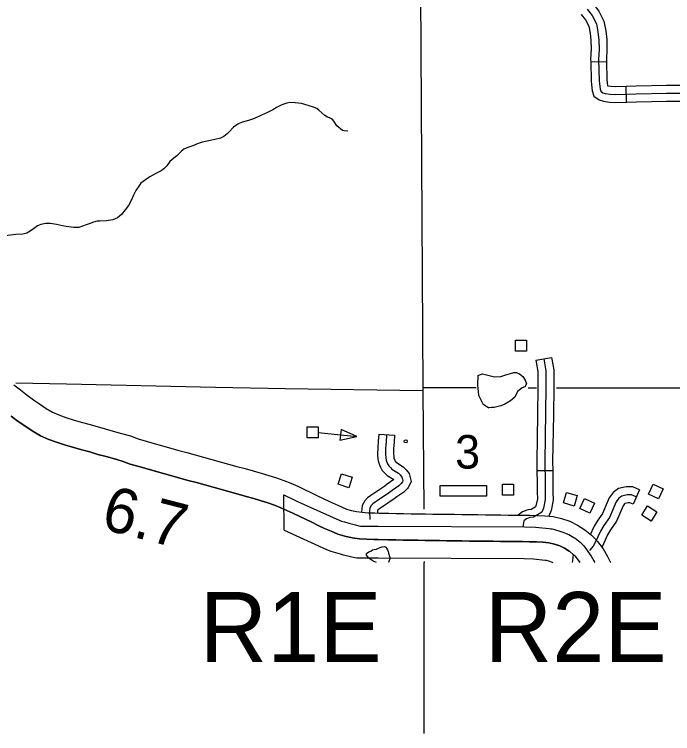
# Model space of a CAD drawing. Extents: x 1369885 to 1370219, y 379980 to 380218.
# Drawn here: x 1370053.81 to 1370078.53, y 380029.29 to 380056.29 of the extents above; entities that cross this region are included whole.
import ezdxf

# ---------------------------------------------------------------- set-up
doc = ezdxf.new("R2010")
doc.units = 0
for name, color, linetype in [('Default', 7, 'Continuous'), ('Level 10', 7, 'Continuous'), ('Level 32', 7, 'Continuous'), ('Level 34', 7, 'Continuous'), ('Level 35', 7, 'Continuous'), ('Level 4', 7, 'Continuous'), ('Level 45', 7, 'Continuous'), ('Level 48', 7, 'Continuous'), ('Level 5', 7, 'Continuous'), ('Level 56', 7, 'Continuous'), ('Level 6', 7, 'Continuous'), ('R_Draft', 7, 'Continuous')]:
    doc.layers.add(name, color=color, linetype=linetype)

msp = doc.modelspace()

# ---------------------------------------------------------------- linework, layer by layer
at = {"layer": 'Level 10'}
for p, q in [((1370061.226, 380039.586), (1370061.226, 380039.586)), ((1370060.964, 380038.627), (1370060.964, 380038.627))]:
    msp.add_line(p, q, dxfattribs=at)
for points in [[(1370053.794, 380042.387), (1370054.048, 380042.195), (1370054.297, 380042.001), (1370054.53, 380041.821), (1370054.761, 380041.667), (1370055.004, 380041.502), (1370055.25, 380041.361), (1370055.486, 380041.254), (1370055.744, 380041.162), (1370056.025, 380041.075), (1370056.315, 380040.99), (1370056.613, 380040.907), (1370056.917, 380040.821), (1370057.221, 380040.733), (1370057.527, 380040.647), (1370057.839, 380040.56), (1370058.174, 380040.465), (1370058.467, 380040.353), (1370058.758, 380040.271), (1370059.067, 380040.184), (1370059.376, 380040.097), (1370059.683, 380040.01), (1370059.988, 380039.925), (1370060.292, 380039.84), (1370060.598, 380039.756), (1370060.91, 380039.672), (1370061.226, 380039.586)], [(1370053.794, 380042.387), (1370054.048, 380042.195), (1370054.297, 380042.001), (1370054.53, 380041.821), (1370054.761, 380041.667), (1370055.004, 380041.502), (1370055.25, 380041.361), (1370055.486, 380041.254), (1370055.744, 380041.162), (1370056.025, 380041.075), (1370056.315, 380040.99), (1370056.613, 380040.907), (1370056.917, 380040.821), (1370057.221, 380040.733), (1370057.527, 380040.647), (1370057.839, 380040.56), (1370058.174, 380040.465), (1370058.467, 380040.353), (1370058.758, 380040.271), (1370059.067, 380040.184), (1370059.376, 380040.097), (1370059.683, 380040.01), (1370059.988, 380039.925), (1370060.292, 380039.84), (1370060.598, 380039.756), (1370060.91, 380039.672), (1370061.226, 380039.586)], [(1370053.688, 380041.215), (1370053.95, 380041.013), (1370054.205, 380040.843), (1370054.476, 380040.658), (1370054.797, 380040.475), (1370055.112, 380040.331), (1370055.43, 380040.218), (1370055.738, 380040.123), (1370056.041, 380040.034), (1370056.344, 380039.949), (1370056.644, 380039.865), (1370056.949, 380039.776), (1370057.259, 380039.69), (1370057.569, 380039.603), (1370057.861, 380039.52), (1370058.155, 380039.408), (1370058.488, 380039.314), (1370058.798, 380039.227), (1370059.105, 380039.14), (1370059.413, 380039.052), (1370059.721, 380038.967), (1370060.028, 380038.881), (1370060.338, 380038.797), (1370060.65, 380038.713), (1370060.964, 380038.627)], [(1370060.964, 380038.627), (1370060.65, 380038.713), (1370060.338, 380038.797), (1370060.028, 380038.881), (1370059.721, 380038.967), (1370059.413, 380039.052), (1370059.105, 380039.14), (1370058.798, 380039.227), (1370058.488, 380039.314), (1370058.155, 380039.408), (1370057.861, 380039.52), (1370057.569, 380039.603), (1370057.259, 380039.69), (1370056.949, 380039.776), (1370056.644, 380039.865), (1370056.344, 380039.949), (1370056.041, 380040.034), (1370055.738, 380040.123), (1370055.43, 380040.218), (1370055.112, 380040.331), (1370054.797, 380040.475), (1370054.476, 380040.658), (1370054.205, 380040.843), (1370053.95, 380041.013), (1370053.688, 380041.215)], [(1370061.226, 380039.586), (1370061.543, 380039.5), (1370061.858, 380039.413), (1370062.17, 380039.326), (1370062.48, 380039.239), (1370062.784, 380039.154), (1370063.079, 380039.072), (1370063.368, 380038.988), (1370063.651, 380038.899), (1370063.929, 380038.799), (1370064.199, 380038.692), (1370064.459, 380038.578), (1370064.705, 380038.461), (1370064.94, 380038.348), (1370065.176, 380038.235), (1370065.411, 380038.12), (1370065.645, 380038.008), (1370065.876, 380037.9), (1370066.092, 380037.802), (1370066.29, 380037.724), (1370066.475, 380037.666), (1370066.666, 380037.627), (1370066.874, 380037.599), (1370067.101, 380037.583), (1370067.35, 380037.574), (1370067.504, 380037.568), (1370067.879, 380037.562), (1370068.155, 380037.557), (1370068.433, 380037.551), (1370068.709, 380037.547), (1370068.986, 380037.542), (1370069.256, 380037.537), (1370069.523, 380037.534), (1370069.792, 380037.531), (1370070.066, 380037.528), (1370070.346, 380037.525), (1370070.632, 380037.52), (1370070.919, 380037.516), (1370071.212, 380037.514), (1370071.506, 380037.51), (1370071.796, 380037.506), (1370072.082, 380037.5), (1370072.36, 380037.496), (1370072.632, 380037.493), (1370072.902, 380037.492), (1370073.173, 380037.489), (1370073.449, 380037.484), (1370073.74, 380037.471), (1370074.05, 380037.437), (1370074.363, 380037.368), (1370074.67, 380037.264), (1370074.963, 380037.122), (1370075.235, 380036.948), (1370075.3, 380036.895)], [(1370061.226, 380039.586), (1370061.543, 380039.5), (1370061.858, 380039.413), (1370062.17, 380039.326), (1370062.48, 380039.239), (1370062.784, 380039.154), (1370063.079, 380039.072), (1370063.368, 380038.988), (1370063.651, 380038.899), (1370063.929, 380038.799), (1370064.199, 380038.692), (1370064.459, 380038.578), (1370064.705, 380038.461), (1370064.94, 380038.348), (1370065.176, 380038.235), (1370065.411, 380038.12), (1370065.645, 380038.008), (1370065.876, 380037.9), (1370066.092, 380037.802), (1370066.29, 380037.724), (1370066.475, 380037.666), (1370066.666, 380037.627), (1370066.874, 380037.599), (1370067.101, 380037.583), (1370067.35, 380037.574), (1370067.504, 380037.568), (1370067.879, 380037.562), (1370068.155, 380037.557), (1370068.433, 380037.551), (1370068.709, 380037.547), (1370068.986, 380037.542), (1370069.256, 380037.537), (1370069.523, 380037.534), (1370069.792, 380037.531), (1370070.066, 380037.528), (1370070.346, 380037.525), (1370070.632, 380037.52), (1370070.919, 380037.516), (1370071.212, 380037.514), (1370071.506, 380037.51), (1370071.796, 380037.506), (1370072.082, 380037.5), (1370072.36, 380037.496), (1370072.632, 380037.493), (1370072.902, 380037.492), (1370073.173, 380037.489), (1370073.449, 380037.484), (1370073.74, 380037.471), (1370074.05, 380037.437), (1370074.363, 380037.368), (1370074.67, 380037.264), (1370074.963, 380037.122), (1370075.235, 380036.948), (1370075.3, 380036.895)], [(1370060.964, 380038.627), (1370061.279, 380038.541), (1370061.592, 380038.454), (1370061.903, 380038.368), (1370062.212, 380038.281), (1370062.518, 380038.196), (1370062.808, 380038.116), (1370063.078, 380038.037), (1370063.333, 380037.956), (1370063.578, 380037.868), (1370063.816, 380037.774), (1370064.046, 380037.673), (1370064.276, 380037.564), (1370064.509, 380037.452), (1370064.742, 380037.34), (1370064.978, 380037.225), (1370065.219, 380037.109), (1370065.461, 380036.996), (1370065.704, 380036.886), (1370065.959, 380036.785), (1370066.227, 380036.702), (1370066.5, 380036.645), (1370066.773, 380036.61), (1370067.046, 380036.59), (1370067.314, 380036.58), (1370067.478, 380036.574), (1370067.862, 380036.568), (1370068.136, 380036.563), (1370068.414, 380036.557), (1370068.693, 380036.552), (1370068.968, 380036.548), (1370069.241, 380036.543), (1370069.513, 380036.539), (1370069.782, 380036.537), (1370070.055, 380036.534), (1370070.332, 380036.531), (1370070.617, 380036.526), (1370070.909, 380036.522), (1370071.201, 380036.52), (1370071.491, 380036.516), (1370071.78, 380036.511), (1370072.065, 380036.506), (1370072.347, 380036.502), (1370072.624, 380036.499), (1370072.893, 380036.498), (1370073.159, 380036.494), (1370073.418, 380036.49), (1370073.663, 380036.479), (1370073.888, 380036.454), (1370074.095, 380036.409), (1370074.293, 380036.342), (1370074.477, 380036.253), (1370074.65, 380036.142), (1370074.671, 380036.125)], [(1370074.671, 380036.125), (1370074.65, 380036.142), (1370074.477, 380036.253), (1370074.293, 380036.342), (1370074.095, 380036.409), (1370073.888, 380036.454), (1370073.663, 380036.479), (1370073.418, 380036.49), (1370073.159, 380036.494), (1370072.893, 380036.498), (1370072.624, 380036.499), (1370072.347, 380036.502), (1370072.065, 380036.506), (1370071.78, 380036.511), (1370071.491, 380036.516), (1370071.201, 380036.52), (1370070.909, 380036.522), (1370070.617, 380036.526), (1370070.332, 380036.531), (1370070.055, 380036.534), (1370069.782, 380036.537), (1370069.513, 380036.539), (1370069.241, 380036.543), (1370068.968, 380036.548), (1370068.693, 380036.552), (1370068.414, 380036.557), (1370068.136, 380036.563), (1370067.862, 380036.568), (1370067.478, 380036.574), (1370067.314, 380036.58), (1370067.046, 380036.59), (1370066.773, 380036.61), (1370066.5, 380036.645), (1370066.227, 380036.702), (1370065.959, 380036.785), (1370065.704, 380036.886), (1370065.461, 380036.996), (1370065.219, 380037.109), (1370064.978, 380037.225), (1370064.742, 380037.34), (1370064.509, 380037.452), (1370064.276, 380037.564), (1370064.046, 380037.673), (1370063.816, 380037.774), (1370063.578, 380037.868), (1370063.333, 380037.956), (1370063.078, 380038.037), (1370062.808, 380038.116), (1370062.518, 380038.196), (1370062.212, 380038.281), (1370061.903, 380038.368), (1370061.592, 380038.454), (1370061.279, 380038.541), (1370060.964, 380038.627)], [(1370075.3, 380036.895), (1370075.487, 380036.743), (1370075.609, 380036.617), (1370075.718, 380036.504), (1370075.923, 380036.233), (1370076.09, 380035.946), (1370076.203, 380035.719)], [(1370075.065, 380035.719), (1370074.962, 380035.856), (1370074.896, 380035.924), (1370074.813, 380036.008), (1370074.671, 380036.125)]]:
    msp.add_lwpolyline(points, dxfattribs=at)
at = {"layer": 'Level 32'}
for p, q in [((1370075.456, 380054.514), (1370076.052, 380054.528)), ((1370076.8, 380053.003), (1370076.783, 380053.6))]:
    msp.add_line(p, q, dxfattribs=at)
for points in [[(1370075.524, 380056.717), (1370075.553, 380056.688), (1370075.768, 380056.412), (1370075.956, 380056.039), (1370076.021, 380055.683), (1370076.061, 380055.351), (1370076.069, 380054.991), (1370076.051, 380054.605), (1370076.052, 380054.528)], [(1370075.329, 380056.49), (1370075.514, 380056.252), (1370075.67, 380055.943), (1370075.726, 380055.638), (1370075.763, 380055.33), (1370075.771, 380054.995), (1370075.752, 380054.608), (1370075.771, 380053.805), (1370075.782, 380053.699), (1370075.808, 380053.491), (1370075.834, 380053.41), (1370075.908, 380053.354), (1370076.005, 380053.324), (1370076.194, 380053.298), (1370076.406, 380053.291), (1370077.168, 380053.312), (1370078.304, 380053.336), (1370079.174, 380053.34)], [(1370075.102, 380056.295), (1370075.105, 380056.292), (1370075.261, 380056.091), (1370075.385, 380055.847), (1370075.431, 380055.593), (1370075.465, 380055.309), (1370075.472, 380054.999), (1370075.454, 380054.612), (1370075.456, 380054.514)], [(1370075.456, 380054.514), (1370075.473, 380053.786), (1370075.486, 380053.665), (1370075.515, 380053.427), (1370075.579, 380053.228), (1370075.771, 380053.084), (1370075.94, 380053.032), (1370076.169, 380053), (1370076.405, 380052.992), (1370076.8, 380053.003)], [(1370076.052, 380054.528), (1370076.069, 380053.825), (1370076.078, 380053.734), (1370076.093, 380053.613), (1370076.22, 380053.596), (1370076.407, 380053.589), (1370076.783, 380053.6)], [(1370076.783, 380053.6), (1370077.16, 380053.61), (1370078.301, 380053.634), (1370078.89, 380053.637)], [(1370076.8, 380053.003), (1370077.175, 380053.014), (1370078.308, 380053.038), (1370078.893, 380053.041)]]:
    msp.add_lwpolyline(points, dxfattribs=at)
at = {"layer": 'Level 34'}
msp.add_lwpolyline([(1370074.8, 380036.022), (1370074.781, 380035.89), (1370074.772, 380035.792), (1370074.766, 380035.719)], dxfattribs=at)
at = {"layer": 'Level 35'}
for points in [[(1370066.331, 380051.916), (1370066.195, 380051.917), (1370066.135, 380051.934), (1370065.927, 380052.114), (1370065.875, 380052.191), (1370065.836, 380052.249), (1370065.772, 380052.337), (1370065.722, 380052.374), (1370065.652, 380052.414), (1370065.575, 380052.442), (1370065.477, 380052.501), (1370065.356, 380052.598), (1370065.243, 380052.703), (1370065.169, 380052.755), (1370065.128, 380052.773), (1370065.051, 380052.809), (1370064.885, 380052.864), (1370064.719, 380052.915), (1370064.594, 380052.948), (1370064.478, 380052.962), (1370064.358, 380052.975), (1370064.155, 380052.988), (1370064.045, 380052.967), (1370063.854, 380052.893), (1370063.687, 380052.808), (1370063.518, 380052.707), (1370063.32, 380052.609), (1370063.099, 380052.51), (1370062.831, 380052.388), (1370062.608, 380052.312), (1370062.361, 380052.243), (1370062.202, 380052.171), (1370062.041, 380052.063), (1370061.88, 380051.879), (1370061.808, 380051.807), (1370061.682, 380051.713), (1370061.55, 380051.65), (1370061.342, 380051.595), (1370061.118, 380051.551), (1370060.87, 380051.498), (1370060.652, 380051.419), (1370060.52, 380051.36), (1370060.328, 380051.302), (1370060.173, 380051.23), (1370060.085, 380051.153), (1370060.014, 380051.078), (1370059.919, 380050.981), (1370059.805, 380050.895), (1370059.652, 380050.771), (1370059.537, 380050.614), (1370059.428, 380050.496), (1370059.329, 380050.423), (1370059.123, 380050.321), (1370058.899, 380050.197), (1370058.734, 380050.081), (1370058.566, 380049.952), (1370058.506, 380049.885), (1370058.37, 380049.682), (1370058.288, 380049.507), (1370058.203, 380049.311), (1370058.093, 380049.122), (1370057.979, 380048.96), (1370057.833, 380048.781), (1370057.684, 380048.657), (1370057.506, 380048.58), (1370057.273, 380048.544), (1370057.027, 380048.535), (1370056.924, 380048.525), (1370056.779, 380048.49), (1370056.615, 380048.425), (1370056.514, 380048.388), (1370056.233, 380048.293), (1370056.193, 380048.287), (1370056.046, 380048.299), (1370055.757, 380048.335), (1370055.621, 380048.356), (1370055.4, 380048.4), (1370055.171, 380048.444), (1370054.988, 380048.442), (1370054.8, 380048.404), (1370054.679, 380048.35), (1370054.53, 380048.246), (1370054.411, 380048.156), (1370054.276, 380048.081), (1370054.127, 380048.045), (1370053.869, 380048.028), (1370053.059, 380047.933)], [(1370071.222, 380042.74), (1370071.393, 380042.797), (1370071.644, 380042.74), (1370071.838, 380042.682), (1370072.078, 380042.705), (1370072.226, 380042.751), (1370072.568, 380042.854), (1370072.671, 380042.854), (1370072.785, 380042.797), (1370072.911, 380042.694), (1370073.002, 380042.557), (1370073.048, 380042.42), (1370072.979, 380042.317), (1370072.888, 380042.271), (1370072.705, 380042.134), (1370072.603, 380041.929), (1370072.443, 380041.78), (1370072.237, 380041.655), (1370072.078, 380041.598), (1370071.827, 380041.54), (1370071.735, 380041.54), (1370071.633, 380041.518)], [(1370071.222, 380042.74), (1370071.21, 380042.374), (1370071.245, 380041.997), (1370071.404, 380041.677), (1370071.633, 380041.518)], [(1370067.417, 380035.719), (1370067.29, 380035.77), (1370067.122, 380035.88), (1370067.041, 380035.99), (1370067.038, 380036.058), (1370067.119, 380036.11), (1370067.2, 380036.136), (1370067.268, 380036.191)], [(1370067.268, 380036.191), (1370067.323, 380036.207), (1370067.41, 380036.22), (1370067.491, 380036.25), (1370067.546, 380036.275), (1370067.62, 380036.308), (1370067.701, 380036.318), (1370067.772, 380036.295), (1370067.792, 380036.259), (1370067.831, 380036.185), (1370067.847, 380036.13), (1370067.86, 380036.071)], [(1370067.86, 380036.071), (1370067.899, 380035.942), (1370067.908, 380035.909), (1370067.912, 380035.851), (1370067.879, 380035.757), (1370067.869, 380035.719)]]:
    msp.add_lwpolyline(points, dxfattribs=at)
at = {"layer": 'Level 4'}
for points in [[(1370069.02, 380065.25), (1370069.029, 380063.666), (1370069.031, 380063.449), (1370069.157, 380042.282), (1370069.158, 380042.172), (1370069.189, 380037.721)], [(1370069.203, 380035.752), (1370069.203, 380035.719)]]:
    msp.add_lwpolyline(points, dxfattribs=at)
at = {"layer": 'Level 45'}
for p, q in [((1370073.402, 380043.309), (1370073.989, 380043.414)), ((1370067.494, 380040.529), (1370068.089, 380040.492)), ((1370073.437, 380039.164), (1370074.033, 380039.173)), ((1370077.291, 380038.45), (1370077.047, 380037.905))]:
    msp.add_line(p, q, dxfattribs=at)
for points in [[(1370073.989, 380043.414), (1370074.074, 380042.943), (1370074.074, 380042.297), (1370074.057, 380041.263)], [(1370073.696, 380043.361), (1370073.776, 380042.916), (1370073.776, 380042.299), (1370073.73, 380039.513), (1370073.741, 380038.707), (1370073.741, 380038.364), (1370073.753, 380038.078), (1370073.684, 380037.759), (1370073.622, 380037.606), (1370073.525, 380037.542), (1370073.308, 380037.416), (1370073.171, 380037.405), (1370073.045, 380037.359), (1370072.943, 380037.279), (1370072.907, 380037.056)], [(1370073.402, 380043.309), (1370073.477, 380042.889), (1370073.477, 380042.302), (1370073.46, 380041.273)], [(1370073.46, 380041.273), (1370073.432, 380039.513), (1370073.437, 380039.164)], [(1370074.057, 380041.263), (1370074.028, 380039.512), (1370074.033, 380039.173)], [(1370067.791, 380040.51), (1370067.775, 380040.251), (1370067.756, 380040.008), (1370067.749, 380039.795), (1370067.762, 380039.639), (1370067.777, 380039.557), (1370067.801, 380039.487), (1370067.827, 380039.421), (1370067.871, 380039.348), (1370067.945, 380039.264), (1370067.989, 380039.225), (1370068.175, 380039.108), (1370068.241, 380039.066), (1370068.306, 380039.001), (1370068.368, 380038.92), (1370068.39, 380038.839), (1370068.4, 380038.788), (1370068.384, 380038.75), (1370068.345, 380038.685), (1370068.248, 380038.591), (1370067.996, 380038.42), (1370067.899, 380038.341), (1370067.435, 380038.031), (1370067.368, 380037.986), (1370067.274, 380037.918), (1370067.212, 380037.853), (1370067.162, 380037.764), (1370067.154, 380037.642), (1370067.16, 380037.328)], [(1370067.494, 380040.529), (1370067.478, 380040.272), (1370067.458, 380040.025), (1370067.451, 380039.787), (1370067.466, 380039.601), (1370067.487, 380039.481), (1370067.521, 380039.384), (1370067.558, 380039.289), (1370067.629, 380039.171), (1370067.734, 380039.053), (1370067.809, 380038.985), (1370068.063, 380038.826)], [(1370068.089, 380040.492), (1370068.073, 380040.23), (1370068.054, 380039.992), (1370068.048, 380039.803), (1370068.059, 380039.678), (1370068.067, 380039.632), (1370068.081, 380039.59), (1370068.096, 380039.552), (1370068.112, 380039.525), (1370068.157, 380039.475), (1370068.168, 380039.464), (1370068.334, 380039.36), (1370068.429, 380039.3), (1370068.531, 380039.198), (1370068.639, 380039.055), (1370068.681, 380038.907), (1370068.71, 380038.753), (1370068.65, 380038.614), (1370068.602, 380038.533)], [(1370073.437, 380039.164), (1370073.443, 380038.704), (1370073.443, 380038.358), (1370073.453, 380038.104), (1370073.398, 380037.847), (1370073.381, 380037.804), (1370073.368, 380037.796), (1370073.216, 380037.708), (1370073.106, 380037.699), (1370073.056, 380037.68)], [(1370074.033, 380039.173), (1370074.04, 380038.709), (1370074.04, 380038.37), (1370074.052, 380038.053), (1370073.971, 380037.67), (1370073.882, 380037.455)], [(1370068.063, 380038.826), (1370067.818, 380038.659), (1370067.722, 380038.581), (1370067.27, 380038.279), (1370067.197, 380038.231), (1370067.076, 380038.143), (1370066.971, 380038.032), (1370066.868, 380037.852), (1370066.852, 380037.601)], [(1370068.602, 380038.533), (1370068.581, 380038.498), (1370068.437, 380038.359), (1370068.174, 380038.18), (1370068.076, 380038.101), (1370067.601, 380037.783), (1370067.538, 380037.741), (1370067.471, 380037.692), (1370067.455, 380037.675), (1370067.448, 380037.569)], [(1370077.291, 380038.45), (1370077.043, 380038.561), (1370076.789, 380038.551), (1370076.506, 380038.489), (1370076.297, 380038.349), (1370076.153, 380038.138), (1370075.9, 380037.556), (1370075.703, 380037.269), (1370075.582, 380037.074)], [(1370077.169, 380038.177), (1370076.985, 380038.26), (1370076.827, 380038.254), (1370076.624, 380038.209), (1370076.51, 380038.133), (1370076.415, 380037.994), (1370076.162, 380037.411), (1370075.953, 380037.107), (1370075.82, 380036.891), (1370075.63, 380036.463), (1370075.554, 380036.333), (1370075.417, 380036.16)], [(1370077.047, 380037.905), (1370076.927, 380037.959), (1370076.865, 380037.956), (1370076.743, 380037.93), (1370076.724, 380037.917), (1370076.678, 380037.849), (1370076.424, 380037.265), (1370076.203, 380036.944), (1370076.09, 380036.76)], [(1370073.056, 380037.68), (1370072.899, 380037.623), (1370072.732, 380037.493)], [(1370075.582, 380037.074), (1370075.556, 380037.031), (1370075.446, 380036.784)], [(1370076.09, 380036.76), (1370076.085, 380036.752), (1370075.884, 380036.299)]]:
    msp.add_lwpolyline(points, dxfattribs=at)
at = {"layer": 'Level 5'}
for points in [[(1370053.868, 380042.457), (1370055.77, 380042.418), (1370061.37, 380042.302)], [(1370061.37, 380042.302), (1370063.98, 380042.249), (1370069.158, 380042.172)], [(1370074.178, 380042.278), (1370080.207, 380042.274), (1370083.889, 380042.335)], [(1370069.157, 380042.282), (1370071.158, 380042.28)], [(1370073.104, 380042.279), (1370073.425, 380042.279)]]:
    msp.add_lwpolyline(points, dxfattribs=at)
at = {"layer": 'Level 56'}
for points in [[(1370072.631, 380043.645), (1370072.631, 380044.059), (1370073.046, 380044.059), (1370073.046, 380043.645)], [(1370064.806, 380040.393), (1370064.806, 380040.807), (1370065.222, 380040.807), (1370065.222, 380040.393)], [(1370066.085, 380040.711), (1370066.041, 380040.307), (1370066.668, 380040.443)], [(1370065.974, 380038.652), (1370066.103, 380039.046), (1370066.498, 380038.917), (1370066.369, 380038.523)], [(1370069.798, 380038.203), (1370069.798, 380038.601), (1370071.539, 380038.601), (1370071.539, 380038.203)], [(1370072.146, 380038.238), (1370072.146, 380038.652), (1370072.561, 380038.652), (1370072.561, 380038.238)], [(1370077.626, 380038.283), (1370077.802, 380038.658), (1370078.178, 380038.481), (1370078.001, 380038.106)], [(1370074.433, 380037.95), (1370074.551, 380038.346), (1370074.949, 380038.228), (1370074.831, 380037.831)], [(1370075.048, 380037.738), (1370075.218, 380038.115), (1370075.597, 380037.944), (1370075.426, 380037.567)], [(1370077.374, 380037.493), (1370077.593, 380037.844), (1370077.945, 380037.624), (1370077.726, 380037.273)]]:
    msp.add_lwpolyline(points, close=True, dxfattribs=at)
msp.add_lwpolyline([(1370065.222, 380040.6), (1370066.668, 380040.443)], dxfattribs=at)
msp.add_circle((1370068.51, 380040.266), 0.0597, dxfattribs=at)
at = {"layer": 'Level 6'}
for points in [[(1370063.944, 380036.926), (1370063.934, 380038.252), (1370064.087, 380038.185), (1370064.248, 380038.11), (1370064.446, 380038.009), (1370066.005, 380037.307), (1370066.097, 380037.27), (1370066.205, 380037.237), (1370066.374, 380037.19), (1370066.474, 380037.161), (1370066.618, 380037.126), (1370066.746, 380037.096), (1370066.808, 380037.083), (1370066.881, 380037.082), (1370067.477, 380037.084), (1370072.972, 380037.056), (1370073.389, 380037.045), (1370073.895, 380036.992), (1370073.959, 380036.982), (1370074.007, 380036.976), (1370074.066, 380036.964), (1370074.135, 380036.944), (1370074.256, 380036.903), (1370074.408, 380036.852), (1370074.538, 380036.805), (1370074.63, 380036.763), (1370074.701, 380036.728), (1370074.823, 380036.654), (1370074.872, 380036.623), (1370074.937, 380036.577), (1370075.003, 380036.527), (1370075.063, 380036.478), (1370075.135, 380036.402), (1370075.182, 380036.35), (1370075.219, 380036.303), (1370075.269, 380036.245), (1370075.351, 380036.132), (1370075.476, 380035.948), (1370075.526, 380035.87), (1370075.577, 380035.776), (1370075.61, 380035.721), (1370075.611, 380035.719)], [(1370063.944, 380036.926), (1370065.538, 380036.208), (1370065.703, 380036.142), (1370065.874, 380036.091), (1370066.049, 380036.042), (1370066.166, 380036.008), (1370066.339, 380035.966), (1370066.49, 380035.93), (1370066.677, 380035.892), (1370066.875, 380035.889), (1370067.476, 380035.891), (1370072.953, 380035.863), (1370073.312, 380035.853), (1370073.741, 380035.808), (1370073.786, 380035.801), (1370073.79, 380035.801), (1370073.877, 380035.772), (1370074.012, 380035.726), (1370074.032, 380035.719)]]:
    msp.add_lwpolyline(points, dxfattribs=at)
at = {"layer": 'R_Draft'}
msp.add_line((1370069.203, 380029.291), (1370069.203, 380035.719), dxfattribs=at)

# ---------------------------------------------------------------- texts
at = {"layer": 'Default'}
for s, p in [(' R1E', (1370059.788, 380031.976)), ('R2E', (1370071.47, 380031.976))]:
    msp.add_text(s, height=2.63, dxfattribs=at).set_placement(p)
at = {"layer": 'Level 48'}
msp.add_text('6.7', height=1.6802, rotation=345.5088, dxfattribs=at).set_placement((1370057.015, 380037))
at = {"layer": 'Level 56'}
msp.add_text('3', height=1.26, dxfattribs=at).set_placement((1370070.365, 380039.241))

doc.saveas('drawing.dxf')
